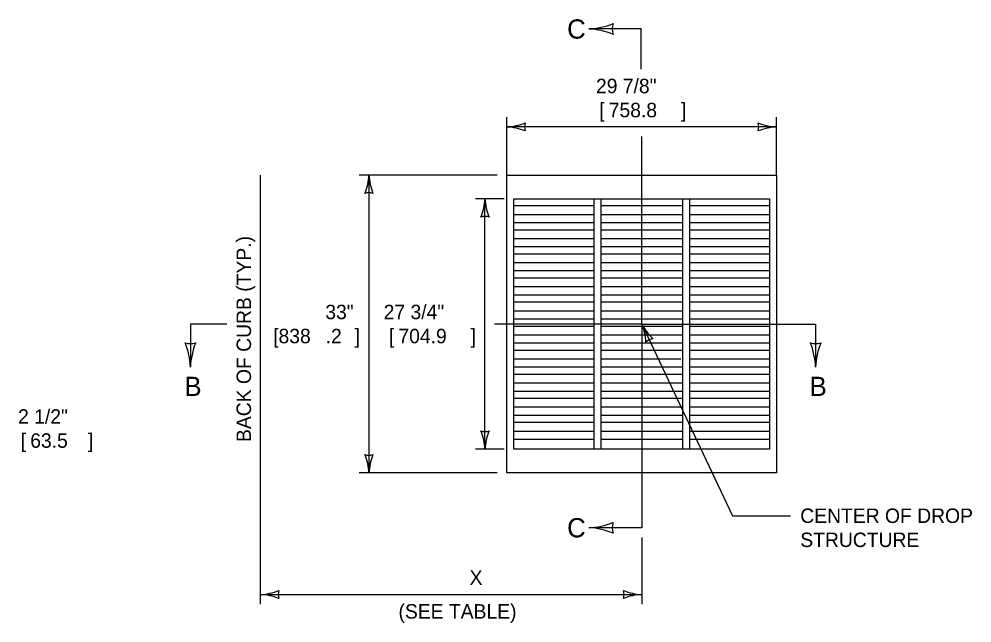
# Model space of a CAD drawing. Extents: x 49991.4 to 50041.6, y 49987.6 to 50011.4.
# Drawn here: x 50032.781 to 50036.741, y 49995.911 to 49998.42 of the extents above; entities that cross this region are included whole.
import ezdxf

# ---------------------------------------------------------------- set-up
doc = ezdxf.new("R2010")
doc.units = 0
for name, color, linetype in [('Level 1', 7, 'Continuous'), ('Level 2', 7, 'Continuous'), ('Level 3', 7, 'Continuous'), ('Level 6', 7, 'Continuous')]:
    doc.layers.add(name, color=color, linetype=linetype)

msp = doc.modelspace()

# ---------------------------------------------------------------- linework, layer by layer
at = {"layer": 'Level 1'}
for p, q in [((50035.1692, 49997.6434), (50034.8371, 49997.6434)), ((50035.1692, 49997.6734), (50035.1692, 49996.6328)), ((50035.1992, 49997.6734), (50035.1992, 49996.6328)), ((50035.5376, 49997.6434), (50035.1992, 49997.6434)), ((50035.5376, 49997.6734), (50035.5376, 49996.6328)), ((50035.5676, 49997.6734), (50035.5676, 49996.6328)), ((50035.8996, 49997.6434), (50035.5676, 49997.6434)), ((50035.1692, 49997.5734), (50034.8371, 49997.5734)), ((50035.5376, 49997.5734), (50035.1992, 49997.5734)), ((50035.8996, 49997.5734), (50035.5676, 49997.5734)), ((50035.1692, 49997.5434), (50034.8371, 49997.5434)), ((50035.5376, 49997.5434), (50035.1992, 49997.5434)), ((50035.8996, 49997.5434), (50035.5676, 49997.5434)), ((50035.1692, 49997.4734), (50034.8371, 49997.4734)), ((50035.1692, 49997.4434), (50034.8371, 49997.4434)), ((50035.5376, 49997.4734), (50035.1992, 49997.4734)), ((50035.5376, 49997.4434), (50035.1992, 49997.4434)), ((50035.8996, 49997.4734), (50035.5676, 49997.4734)), ((50035.8996, 49997.4434), (50035.5676, 49997.4434)), ((50035.1692, 49997.3734), (50034.8371, 49997.3734)), ((50035.5376, 49997.3734), (50035.1992, 49997.3734)), ((50035.8996, 49997.3734), (50035.5676, 49997.3734)), ((50035.1692, 49997.3434), (50034.8371, 49997.3434)), ((50035.5376, 49997.3434), (50035.1992, 49997.3434)), ((50035.8996, 49997.3434), (50035.5676, 49997.3434)), ((50035.1692, 49997.2734), (50034.8371, 49997.2734)), ((50035.1692, 49997.2434), (50034.8371, 49997.2434)), ((50035.5376, 49997.2734), (50035.1992, 49997.2734)), ((50035.5376, 49997.2434), (50035.1992, 49997.2434)), ((50035.8996, 49997.2734), (50035.5676, 49997.2734)), ((50035.8996, 49997.2434), (50035.5676, 49997.2434)), ((50035.1692, 49997.1734), (50034.8371, 49997.1734)), ((50035.5376, 49997.1734), (50035.1992, 49997.1734)), ((50035.8996, 49997.1734), (50035.5676, 49997.1734)), ((50035.1692, 49997.1434), (50034.8371, 49997.1434)), ((50035.5376, 49997.1434), (50035.1992, 49997.1434)), ((50035.8996, 49997.1434), (50035.5676, 49997.1434)), ((50035.1692, 49997.0734), (50034.8371, 49997.0734)), ((50035.1692, 49997.0434), (50034.8371, 49997.0434)), ((50035.5376, 49997.0734), (50035.1992, 49997.0734)), ((50035.5376, 49997.0434), (50035.1992, 49997.0434)), ((50035.8996, 49997.0734), (50035.5676, 49997.0734)), ((50035.8996, 49997.0434), (50035.5676, 49997.0434)), ((50035.1692, 49996.9734), (50034.8371, 49996.9734)), ((50035.5376, 49996.9734), (50035.1992, 49996.9734)), ((50035.8996, 49996.9734), (50035.5676, 49996.9734)), ((50035.1692, 49996.9434), (50034.8371, 49996.9434)), ((50035.5376, 49996.9434), (50035.1992, 49996.9434)), ((50035.8996, 49996.9434), (50035.5676, 49996.9434)), ((50035.1692, 49996.8734), (50034.8371, 49996.8734)), ((50035.1692, 49996.8434), (50034.8371, 49996.8434)), ((50035.5376, 49996.8734), (50035.1992, 49996.8734)), ((50035.5376, 49996.8434), (50035.1992, 49996.8434)), ((50035.8996, 49996.8734), (50035.5676, 49996.8734)), ((50035.8996, 49996.8434), (50035.5676, 49996.8434)), ((50035.1692, 49996.7734), (50034.8371, 49996.7734)), ((50035.5376, 49996.7734), (50035.1992, 49996.7734)), ((50035.8996, 49996.7734), (50035.5676, 49996.7734)), ((50035.1692, 49996.7434), (50034.8371, 49996.7434)), ((50035.5376, 49996.7434), (50035.1992, 49996.7434)), ((50035.8996, 49996.7434), (50035.5676, 49996.7434)), ((50035.1692, 49996.6734), (50034.8371, 49996.6734)), ((50035.5376, 49996.6734), (50035.1992, 49996.6734)), ((50035.8996, 49996.6734), (50035.5676, 49996.6734))]:
    msp.add_line(p, q, dxfattribs=at)
for points in [[(50034.8082, 49997.7719), (50035.9285, 49997.7719), (50035.9285, 49996.5344), (50034.8082, 49996.5344)], [(50034.8371, 49996.6328), (50034.8371, 49997.6734), (50035.8996, 49997.6734), (50035.8996, 49996.6328)]]:
    msp.add_lwpolyline(points, close=True, dxfattribs=at)
for points in [[(50034.8371, 49997.6084), (50035.1692, 49997.6084)], [(50035.1992, 49997.6084), (50035.5376, 49997.6084)], [(50035.5676, 49997.6084), (50035.8996, 49997.6084)], [(50034.8371, 49997.5084), (50035.1692, 49997.5084)], [(50035.1992, 49997.5084), (50035.5376, 49997.5084)], [(50035.5676, 49997.5084), (50035.8996, 49997.5084)], [(50034.8371, 49997.4084), (50035.1692, 49997.4084)], [(50035.1992, 49997.4084), (50035.5376, 49997.4084)], [(50035.5676, 49997.4084), (50035.8996, 49997.4084)], [(50034.8371, 49997.3084), (50035.1692, 49997.3084)], [(50035.1992, 49997.3084), (50035.5376, 49997.3084)], [(50035.5676, 49997.3084), (50035.8996, 49997.3084)], [(50034.8371, 49997.2084), (50035.1692, 49997.2084)], [(50035.1992, 49997.2084), (50035.5376, 49997.2084)], [(50035.5676, 49997.2084), (50035.8996, 49997.2084)], [(50034.8371, 49997.1084), (50035.1692, 49997.1084)], [(50035.1992, 49997.1084), (50035.5376, 49997.1084)], [(50035.5676, 49997.1084), (50035.8996, 49997.1084)], [(50034.8371, 49997.0084), (50035.1692, 49997.0084)], [(50035.1992, 49997.0084), (50035.5312, 49997.0084)], [(50035.5676, 49997.0084), (50035.8996, 49997.0084)], [(50034.8371, 49996.9084), (50035.1692, 49996.9084)], [(50035.1992, 49996.9084), (50035.5376, 49996.9084)], [(50035.5676, 49996.9084), (50035.8996, 49996.9084)], [(50034.8371, 49996.8084), (50035.1692, 49996.8084)], [(50035.1992, 49996.8084), (50035.5376, 49996.8084)], [(50035.5676, 49996.8084), (50035.8996, 49996.8084)], [(50034.8371, 49996.7084), (50035.1692, 49996.7084)], [(50035.1992, 49996.7084), (50035.5376, 49996.7084)], [(50035.5676, 49996.7084), (50035.8996, 49996.7084)]]:
    msp.add_lwpolyline(points, dxfattribs=at)
at = {"layer": 'Level 3'}
for p, q in [((50034.8082, 49997.7719), (50034.8082, 49998.0119)), ((50035.9285, 49997.7719), (50035.9285, 49998.0119)), ((50035.9285, 49997.9719), (50034.8082, 49997.9719)), ((50033.7847, 49995.9894), (50033.7847, 49997.7719)), ((50034.7682, 49997.7719), (50034.1948, 49997.7719)), ((50034.2348, 49997.7719), (50034.2348, 49996.5344)), ((50034.7971, 49997.6734), (50034.6771, 49997.6734)), ((50034.7171, 49996.6328), (50034.7171, 49997.6734)), ((50035.3684, 49997.1531), (50035.7452, 49996.3566)), ((50034.7971, 49996.6328), (50034.6771, 49996.6328)), ((50034.7682, 49996.5344), (50034.1948, 49996.5344)), ((50035.7452, 49996.3566), (50035.9875, 49996.3566)), ((50035.3684, 49996.2667), (50035.3684, 49995.9894)), ((50033.7847, 49996.0294), (50035.3684, 49996.0294))]:
    msp.add_line(p, q, dxfattribs=at)
for centre, radius, start, end in [((50035.1329, 49998.689), 0.3107, 272.8273, 292.0772), ((50035.3192, 49998.3787), 0.073, 162.1388, 197.8612), ((50035.1361, 49998.0825), 0.2964, 67.456, 87.6395), ((50034.7967, 49998.2046), 0.233, 272.8273, 292.0772), ((50034.7967, 49998.2046), 0.233, 272.8273, 292.0772), ((50034.7991, 49997.7497), 0.2223, 67.456, 87.6395), ((50034.7991, 49997.7497), 0.2223, 67.456, 87.6395), ((50034.9364, 49997.9719), 0.0548, 162.1388, 197.8612), ((50034.9364, 49997.9719), 0.0548, 162.1388, 197.8612), ((50035.9377, 49998.194), 0.2223, 247.456, 267.6395), ((50035.8003, 49997.9719), 0.0548, 342.1388, 17.8612), ((50035.94, 49997.7392), 0.233, 92.8273, 112.0772), ((50034.0126, 49997.781), 0.2223, 337.456, 357.6395), ((50034.4675, 49997.7834), 0.233, 182.8273, 202.0772), ((50034.2348, 49997.6436), 0.0548, 72.1388, 107.8612), ((50034.495, 49997.6826), 0.2223, 337.456, 357.6395), ((50034.495, 49997.6826), 0.2223, 337.456, 357.6395), ((50034.9498, 49997.6849), 0.233, 182.8273, 202.0772), ((50034.9498, 49997.6849), 0.233, 182.8273, 202.0772), ((50034.7171, 49997.5452), 0.0548, 72.1388, 107.8612), ((50034.7171, 49997.5452), 0.0548, 72.1388, 107.8612), ((50035.1637, 49997.0664), 0.2223, 2.7736, 22.9571), ((50035.5738, 49997.263), 0.233, 208.1449, 227.3947), ((50035.4232, 49997.0372), 0.0548, 97.4564, 133.1787), ((50033.4927, 49997.1449), 0.073, 252.1388, 287.8612), ((50033.1825, 49996.9587), 0.3107, 2.8273, 22.0772), ((50033.7889, 49996.9618), 0.2964, 157.456, 177.6395), ((50036.0912, 49997.1449), 0.073, 252.1388, 287.8612), ((50035.7809, 49996.9587), 0.3107, 2.8273, 22.0772), ((50036.3874, 49996.9618), 0.2964, 157.456, 177.6395), ((50034.7171, 49996.761), 0.0548, 252.1388, 287.8612), ((50034.4844, 49996.6213), 0.233, 2.8273, 22.0772), ((50034.7171, 49996.761), 0.0548, 252.1388, 287.8612), ((50034.4844, 49996.6213), 0.233, 2.8273, 22.0772), ((50034.9393, 49996.6236), 0.2223, 157.456, 177.6395), ((50034.9393, 49996.6236), 0.2223, 157.456, 177.6395), ((50034.2348, 49996.6626), 0.0548, 252.1388, 287.8612), ((50034.0021, 49996.5229), 0.233, 2.8273, 22.0772), ((50034.2348, 49996.6626), 0.0548, 252.1388, 287.8612), ((50034.0021, 49996.5229), 0.233, 2.8273, 22.0772), ((50034.4569, 49996.5252), 0.2223, 157.456, 177.6395), ((50034.4569, 49996.5252), 0.2223, 157.456, 177.6395), ((50035.1329, 49996.617), 0.3107, 272.8273, 292.0772), ((50035.3192, 49996.3067), 0.073, 162.1388, 197.8612), ((50035.1361, 49996.0105), 0.2964, 67.456, 87.6395), ((50033.7732, 49996.2621), 0.233, 272.8273, 292.0772), ((50033.7732, 49996.2621), 0.233, 272.8273, 292.0772), ((50033.7756, 49995.8072), 0.2223, 67.456, 87.6395), ((50033.7756, 49995.8072), 0.2223, 67.456, 87.6395), ((50033.9129, 49996.0294), 0.0548, 162.1388, 197.8612), ((50033.9129, 49996.0294), 0.0548, 162.1388, 197.8612), ((50035.3775, 49996.2515), 0.2223, 247.456, 267.6395), ((50035.2402, 49996.0294), 0.0548, 342.1388, 17.8612), ((50035.3799, 49995.7966), 0.233, 92.8273, 112.0772)]:
    msp.add_arc(centre, radius, start, end, dxfattribs=at)
at = {"layer": 'Level 6'}
for p, q in [((50035.3663, 49998.3787), (50035.1483, 49998.3787)), ((50035.3663, 49998.2119), (50035.3663, 49998.3787)), ((50035.3684, 49997.1531), (50035.3684, 49997.9319)), ((50035.3684, 49997.1531), (50034.7571, 49997.1531)), ((50035.3684, 49997.1531), (50035.3684, 49996.3067)), ((50035.3684, 49996.3067), (50035.1483, 49996.3067))]:
    msp.add_line(p, q, dxfattribs=at)
for points in [[(50033.6447, 49997.1531), (50033.4927, 49997.1531), (50033.4927, 49996.974)], [(50035.3684, 49997.1531), (50036.0912, 49997.1531), (50036.0912, 49996.974)]]:
    msp.add_lwpolyline(points, dxfattribs=at)

# ---------------------------------------------------------------- texts
at = {"layer": 'Level 2'}
for s, height, p in [('C', 0.08, (50035.0585, 49998.3387)), ('29 7/8"', 0.06, (50035.1785, 49998.1119)), ('[', 0.06, (50035.1917, 49998.0119)), ('758.8', 0.06, (50035.2314, 49998.0119)), (']', 0.06, (50035.5314, 49998.0119)), ('33"', 0.06, (50034.0535, 49997.1731)), ('27 3/4"', 0.06, (50034.2959, 49997.1731)), ('[838', 0.06, (50033.8367, 49997.0731)), ('.2', 0.06, (50034.0549, 49997.0731)), (']', 0.06, (50034.1749, 49997.0731)), ('[', 0.06, (50034.3176, 49997.0731)), ('704.9', 0.06, (50034.3573, 49997.0731)), (']', 0.06, (50034.6573, 49997.0731)), ('B', 0.08, (50033.4679, 49996.854)), ('B', 0.08, (50036.0663, 49996.854)), ('2 1/2"', 0.06, (50032.7766, 49996.7389)), ('[', 0.06, (50032.7874, 49996.6389)), ('63.5', 0.06, (50032.8271, 49996.6389)), (']', 0.06, (50033.0671, 49996.6389)), ('CENTER OF DROP', 0.06, (50036.0275, 49996.3266)), ('C', 0.08, (50035.0585, 49996.2667)), ('STRUCTURE', 0.06, (50036.0275, 49996.2266)), ('X', 0.06, (50034.6532, 49996.0694)), ('(SEE TABLE)', 0.06, (50034.3576, 49995.9294))]:
    msp.add_text(s, height=height, dxfattribs=at).set_placement(p)
msp.add_text('BACK OF CURB (TYP.)', height=0.06, rotation=90, dxfattribs=at).set_placement((50033.7447, 49996.6629))

doc.saveas('drawing.dxf')
